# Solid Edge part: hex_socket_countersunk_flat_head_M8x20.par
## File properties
Author: morva
Template: iso metric part.par
Last saved by: morva
Revision: 27
Application: Solid Edge
Density: 7833.000 kg/m^3
Accuracy: 0.990
Username: morva
Material: Steel
Face Style: Steel
Fill Style: ANSI32(Steel)
Virtual Style: Machined steel
Grouping: Metals\Steel
LibraryName: Materials
Coef. of Thermal Exp: 1.3e-05
Thermal Conductivity: 32.0
Specific Heat: 481.0
Modulus of Elasticity: 199947953000.0
Poisson's Ratio: 0.29
Yield Stress: 262000766.0
Ultimate Stress: 358527364.0
Elongation: 0.0
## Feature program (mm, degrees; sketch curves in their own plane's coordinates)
body "unnamed Body 1"
thread "unnamed Thread 1"
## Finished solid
Body 1: solid body, 13 faces, 23 edges, 12 vertices.
  Faces by surface: plane 9, cone 2, cylinder 2
  Edges by curve: line 18, circle 5
Bounding box of the edges (mm): 16.000 x 16.000 x 20.000, from (-8, -8, -15.6) to (8, 8, 4.4).
Cylindrical faces by radius (mm): R4 x1, R8 x1
Conical faces (half-angle, radius in mm at the cone's reference point): 45 deg R3.25 x1, 45 deg R8.0001 x1
Planar faces by outward normal: +y 1, +z 2, -y 1, -z 1, oblique 4
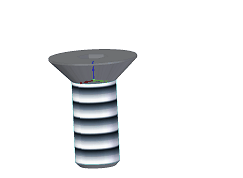
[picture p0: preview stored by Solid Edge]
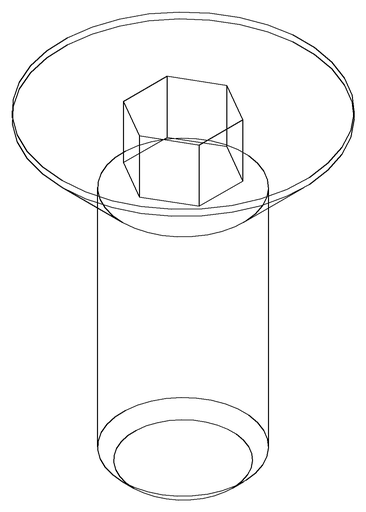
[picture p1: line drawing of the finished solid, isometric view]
